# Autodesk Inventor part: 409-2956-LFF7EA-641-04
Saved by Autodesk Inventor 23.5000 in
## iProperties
Created: 2010-06
Part Number: 409-2956-LFF7EA-641-04
Cost Center: 0 lbmass
Material: A1011 HR STEEL
Document SubType Name: Sheet Metal
Designer: S. Boerckel
Authority: 0 in^3
Mass: 8500.45 g
Surface Area: 6468.78 cm^2
Volume: 1081.48 cm^3
Density: 7.86 g/cm^3
Sheet Metal Rule: 10GA
Description: PRESSURE DIFFERNTIAL PLATE
Flat Pattern Width: 59.69 cm
Flat Pattern Length: 59.69 cm
Flat Pattern Area: 3562.9 cm^2
Sheet Metal Width: 23.5000 in
Sheet Metal Length: 552.2500 in^2
User Status: BURN
SaveDate: 2008-01-15
SaveTime: 10:24
FileName: Sheet Metal
Wide: =<Flat Pattern Width>cm
Length: =<Flat Pattern Length>cm
Thickness: 0.1345 in
SMR: =<Sheet Metal Rule> - <Material>
Author: S. Boerckel
Revision Number: B
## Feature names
1. Hole1
2. Hole2
3. Hole3
4. Hole4
5. Rectangular Pattern1
6. Hole6
7. Plate1
